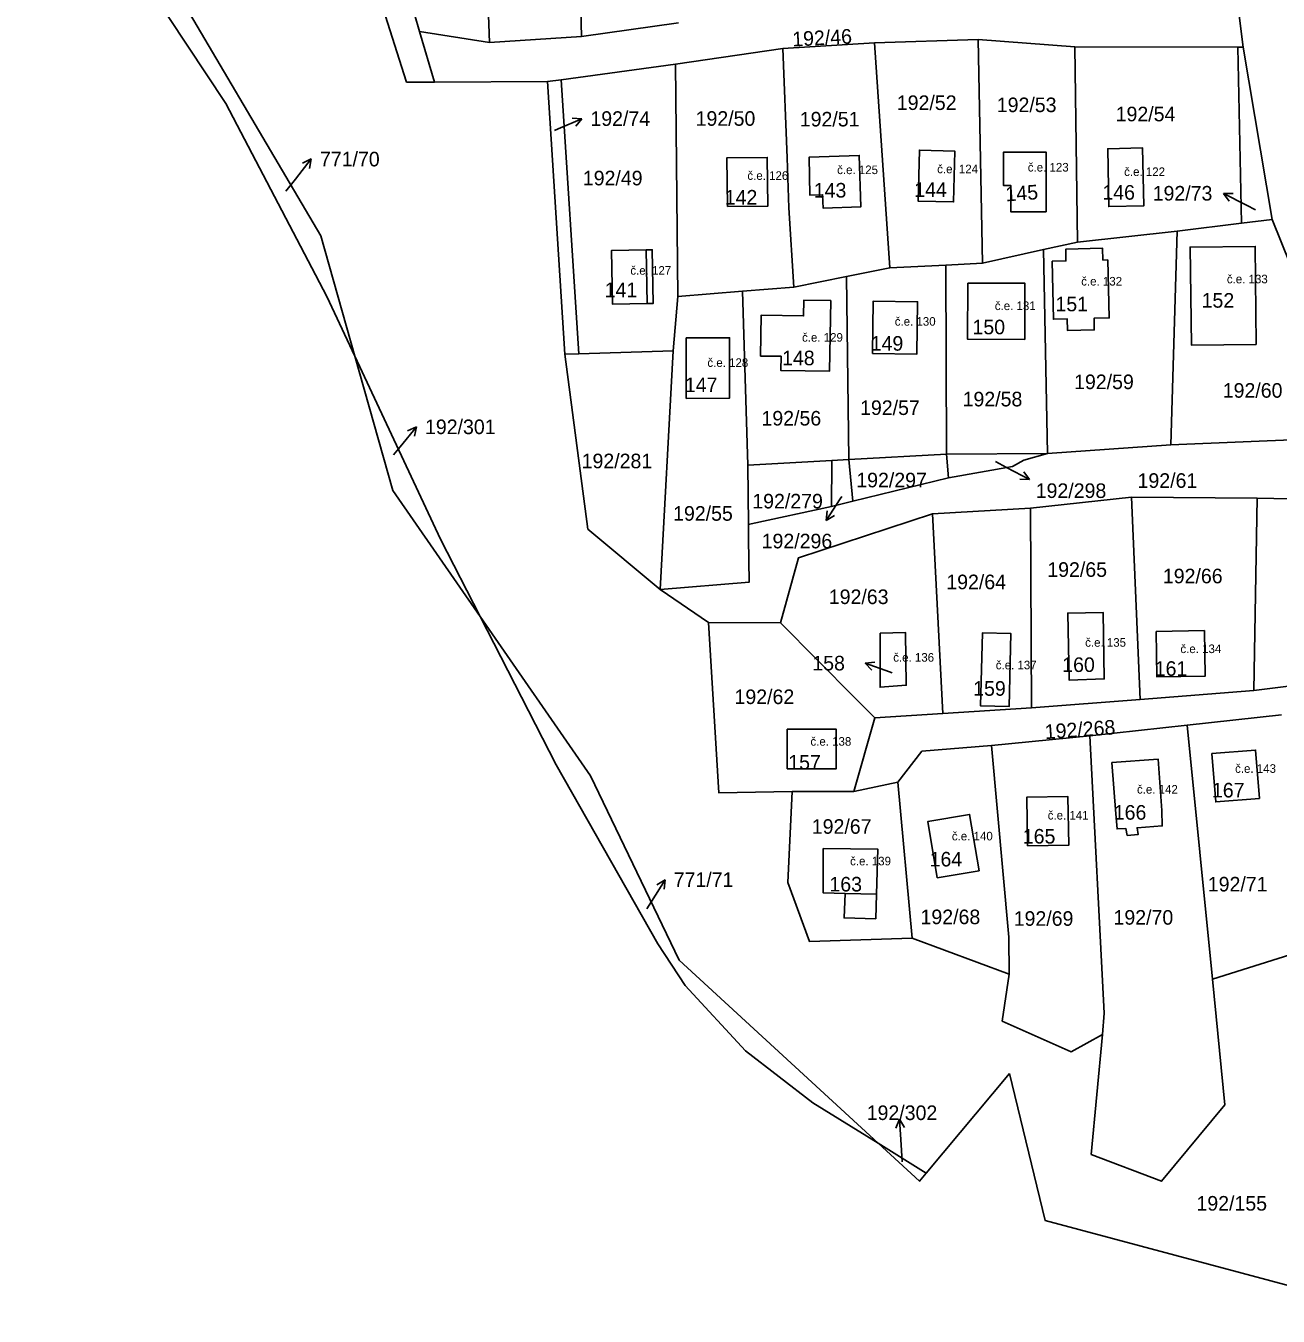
# Model space of a CAD drawing. Extents: x -887272 to -877616, y -1026687 to -1019819.
# Drawn here: x -882540.1 to -882394.3, y -1024320.7 to -1024170.3 of the extents above; entities that cross this region are included whole.
import ezdxf

# ---------------------------------------------------------------- set-up
doc = ezdxf.new("R2010")
doc.units = 0
for name, color, linetype in [('Definiční body', 7, 'Continuous'), ('Hranice parcel', 7, 'Continuous'), ('Parcelní čísla', 7, 'Continuous'), ('Polygon budovy', 7, 'Continuous'), ('Pop  PČ popisy', 7, 'Continuous'), ('Vnitřní kresba', 7, 'Continuous')]:
    doc.layers.add(name, color=color, linetype=linetype)

msp = doc.modelspace()

# ---------------------------------------------------------------- linework, layer by layer
at = {"layer": 'Hranice parcel'}
for p, q in [((-882487.23, -1024142.35), (-882486.14, -1024172.29)), ((-882476.32, -1024141.77), (-882475.42, -1024171.58)), ((-882398.41, -1024172.81), (-882399.41, -1024164.66)), ((-882475.42, -1024171.58), (-882464.13, -1024169.99)), ((-882494.31, -1024171), (-882486.14, -1024172.29)), ((-882492.56, -1024176.88), (-882494.31, -1024171)), ((-882486.14, -1024172.29), (-882475.42, -1024171.58)), ((-882452, -1024172.98), (-882441.31, -1024172.32)), ((-882441.31, -1024172.32), (-882429.24, -1024171.93)), ((-882439.54, -1024198.54), (-882441.31, -1024172.32)), ((-882429.24, -1024171.93), (-882417.98, -1024172.8)), ((-882428.76, -1024197.98), (-882429.24, -1024171.93)), ((-882464.49, -1024174.79), (-882452, -1024172.98)), ((-882417.98, -1024172.8), (-882399, -1024172.81)), ((-882417.69, -1024195.54), (-882417.98, -1024172.8)), ((-882399, -1024172.81), (-882398.41, -1024172.81)), ((-882398.58, -1024193.32), (-882399, -1024172.81)), ((-882395.01, -1024192.91), (-882398.41, -1024172.81)), ((-882477.79, -1024176.61), (-882464.49, -1024174.79)), ((-882464.21, -1024201.86), (-882464.49, -1024174.79)), ((-882492.56, -1024176.88), (-882479.41, -1024176.83)), ((-882479.41, -1024176.83), (-882477.79, -1024176.61)), ((-882479.41, -1024176.83), (-882477.36, -1024208.58)), ((-882477.79, -1024176.61), (-882475.73, -1024208.53)), ((-882406.07, -1024194.26), (-882398.58, -1024193.32)), ((-882395.01, -1024192.91), (-882398.58, -1024193.32)), ((-882384.85, -1024218.23), (-882395.01, -1024192.91)), ((-882417.69, -1024195.54), (-882406.07, -1024194.26)), ((-882406.81, -1024219.16), (-882406.07, -1024194.26)), ((-882428.76, -1024197.98), (-882421.63, -1024196.41)), ((-882421.63, -1024196.41), (-882417.69, -1024195.54)), ((-882421.19, -1024220.14), (-882421.63, -1024196.41)), ((-882433.01, -1024198.2), (-882428.76, -1024197.98)), ((-882444.57, -1024199.55), (-882439.54, -1024198.54)), ((-882439.54, -1024198.54), (-882433.01, -1024198.2)), ((-882432.93, -1024220.23), (-882433.01, -1024198.2)), ((-882456.7, -1024201.26), (-882450.72, -1024200.78)), ((-882450.72, -1024200.78), (-882444.57, -1024199.55)), ((-882444.31, -1024220.86), (-882444.57, -1024199.55)), ((-882464.78, -1024208.18), (-882464.21, -1024201.86)), ((-882464.21, -1024201.86), (-882456.7, -1024201.26)), ((-882456.08, -1024221.52), (-882456.7, -1024201.26)), ((-882477.36, -1024208.58), (-882475.73, -1024208.53)), ((-882475.73, -1024208.53), (-882464.78, -1024208.18)), ((-882464.78, -1024208.18), (-882466.28, -1024236)), ((-882441.55, -1024208.49), (-882436.39, -1024208.57)), ((-882463.24, -1024213.74), (-882458.22, -1024213.73)), ((-882406.81, -1024219.16), (-882384.85, -1024218.23)), ((-882444.31, -1024220.86), (-882432.93, -1024220.23)), ((-882432.93, -1024220.23), (-882421.19, -1024220.14)), ((-882432.7, -1024223), (-882432.93, -1024220.23)), ((-882421.19, -1024220.14), (-882406.81, -1024219.16)), ((-882456.08, -1024221.52), (-882446.3, -1024220.97)), ((-882456, -1024228.42), (-882456.08, -1024221.52)), ((-882446.3, -1024220.97), (-882444.31, -1024220.86)), ((-882443.83, -1024225.73), (-882444.31, -1024220.86)), ((-882443.83, -1024225.73), (-882432.7, -1024223)), ((-882446.34, -1024226.32), (-882443.83, -1024225.73)), ((-882423.15, -1024226.52), (-882434.56, -1024227.19)), ((-882411.4, -1024225.24), (-882423.15, -1024226.52)), ((-882423.04, -1024249.77), (-882423.15, -1024226.52)), ((-882410.38, -1024248.8), (-882411.4, -1024225.24)), ((-882396.78, -1024225.38), (-882411.4, -1024225.24)), ((-882397.17, -1024247.78), (-882396.78, -1024225.38)), ((-882396.78, -1024225.38), (-882382.84, -1024225.57)), ((-882433.35, -1024250.44), (-882434.56, -1024227.19)), ((-882455.98, -1024230.05), (-882456, -1024228.42)), ((-882466.28, -1024236), (-882460.64, -1024239.85)), ((-882452.28, -1024239.89), (-882460.64, -1024239.85)), ((-882423.04, -1024249.77), (-882410.38, -1024248.8)), ((-882410.38, -1024248.8), (-882397.17, -1024247.78)), ((-882441.28, -1024250.96), (-882433.35, -1024250.44)), ((-882433.35, -1024250.44), (-882423.04, -1024249.77)), ((-882393.92, -1024250.6), (-882404.93, -1024251.81)), ((-882443.73, -1024259.52), (-882441.28, -1024250.96)), ((-882404.93, -1024251.81), (-882416.23, -1024253.06)), ((-882401.95, -1024281.38), (-882404.93, -1024251.81)), ((-882416.23, -1024253.06), (-882427.71, -1024254.18)), ((-882450.92, -1024259.54), (-882443.73, -1024259.52)), ((-882438.6, -1024258.43), (-882443.73, -1024259.52)), ((-882436.92, -1024276.61), (-882438.6, -1024258.43)), ((-882434.02, -1024269.59), (-882429.14, -1024268.77)), ((-882436.92, -1024276.61), (-882425.64, -1024280.82)), ((-882401.95, -1024281.38), (-882392.22, -1024278.32)), ((-882435.31, -1024303.99), (-882425.59, -1024292.38)), ((-882435.31, -1024303.99), (-882440.89, -1024300.52))]:
    msp.add_line(p, q, dxfattribs=at)
for points in [[(-882497.59, -1024143.48), (-882497.2, -1024160.85), (-882494.31, -1024171)], [(-882501.82, -1024208.81), (-882505.78, -1024194.82), (-882525.14, -1024161.92), (-882540.14, -1024146.21)], [(-882540.14, -1024146.21), (-882538.86, -1024147.89), (-882532.4, -1024155.87), (-882516.84, -1024179.4), (-882505.08, -1024201.85), (-882501.82, -1024208.81)], [(-882514.25, -1024146.09), (-882509.29, -1024158.43), (-882505.52, -1024158.39), (-882501.29, -1024159.64), (-882495.81, -1024176.89), (-882492.56, -1024176.88)], [(-882450.72, -1024200.78), (-882451.31, -1024191.54), (-882451.49, -1024185.7), (-882452, -1024172.98)], [(-882458.45, -1024191.4), (-882453.75, -1024191.36), (-882453.8, -1024185.66), (-882458.5, -1024185.7), (-882458.45, -1024191.4)], [(-882443.09, -1024185.44), (-882448.92, -1024185.62), (-882448.86, -1024190.05), (-882447.36, -1024190.01), (-882447.31, -1024191.56), (-882442.91, -1024191.42), (-882443.09, -1024185.44)], [(-882432.12, -1024190.85), (-882431.98, -1024184.92), (-882436.1, -1024184.82), (-882436.24, -1024190.75), (-882432.12, -1024190.85)], [(-882426.3, -1024185.04), (-882426.31, -1024188.92), (-882425.46, -1024188.92), (-882425.45, -1024192), (-882421.34, -1024192), (-882421.34, -1024185.05), (-882426.3, -1024185.04)], [(-882410.1, -1024184.56), (-882414.17, -1024184.65), (-882414.04, -1024191.4), (-882409.97, -1024191.32), (-882410.1, -1024184.56)], [(-882471.96, -1024196.52), (-882471.84, -1024202.76), (-882467.79, -1024202.68), (-882467.09, -1024202.67), (-882467.19, -1024196.43), (-882467.91, -1024196.44), (-882471.96, -1024196.52)], [(-882425.59, -1024292.38), (-882421.44, -1024309.52), (-882387.34, -1024318.62), (-882335.2, -1024317.62), (-882324.6, -1024318.36), (-882301.38, -1024320.66), (-882228.26, -1024295.72), (-882166.04, -1024261.72), (-882132.4, -1024219.02), (-882083.16, -1024195.4)], [(-882413.98, -1024204.36), (-882414.17, -1024197.61), (-882414.72, -1024197.63), (-882414.77, -1024196.25), (-882419.06, -1024196.36), (-882419.03, -1024197.72), (-882420.63, -1024197.76), (-882420.48, -1024204.51), (-882418.87, -1024204.47), (-882418.84, -1024205.83), (-882415.73, -1024205.76), (-882415.76, -1024204.4), (-882413.98, -1024204.36)], [(-882396.87, -1024207.45), (-882396.99, -1024196.04), (-882404.57, -1024196.12), (-882404.42, -1024207.52), (-882396.87, -1024207.45)], [(-882430.47, -1024200.31), (-882430.5, -1024206.83), (-882423.82, -1024206.86), (-882423.82, -1024200.3), (-882430.47, -1024200.31)], [(-882454.59, -1024208.81), (-882452.2, -1024208.83), (-882452.23, -1024210.47), (-882446.58, -1024210.58), (-882446.41, -1024202.35), (-882449.54, -1024202.29), (-882449.57, -1024204.13), (-882454.5, -1024204.04), (-882454.59, -1024208.81)], [(-882436.39, -1024208.57), (-882436.3, -1024202.48), (-882441.46, -1024202.4), (-882441.55, -1024208.49)], [(-882458.22, -1024213.73), (-882458.2, -1024206.68), (-882463.25, -1024206.69), (-882463.24, -1024213.74)], [(-882501.82, -1024208.81), (-882497.39, -1024224.47), (-882487.23, -1024239.16)], [(-882487.23, -1024239.16), (-882491.84, -1024230.13), (-882501.82, -1024208.81)], [(-882477.36, -1024208.58), (-882474.69, -1024228.97), (-882466.28, -1024236)], [(-882432.7, -1024223), (-882425.25, -1024221.66), (-882423.95, -1024220.93), (-882421.19, -1024220.14)], [(-882446.34, -1024226.32), (-882446.3, -1024221.18), (-882446.3, -1024220.97)], [(-882456, -1024228.42), (-882455.67, -1024228.35), (-882446.34, -1024226.32)], [(-882434.56, -1024227.19), (-882450.17, -1024232.3), (-882452.28, -1024239.89)], [(-882466.28, -1024236), (-882455.92, -1024235.15), (-882455.98, -1024230.05)], [(-882440.89, -1024300.52), (-882464.08, -1024279.19), (-882474.4, -1024257.7), (-882487.23, -1024239.16)], [(-882487.23, -1024239.16), (-882478.4, -1024256.44), (-882466.55, -1024277.28), (-882463.36, -1024282.12), (-882456.33, -1024289.73), (-882448.49, -1024295.79), (-882440.89, -1024300.52)], [(-882460.64, -1024239.85), (-882459.44, -1024259.7), (-882450.92, -1024259.54)], [(-882441.28, -1024250.96), (-882443.66, -1024248.58), (-882452.28, -1024239.89)], [(-882418.81, -1024238.75), (-882418.66, -1024246.56), (-882414.56, -1024246.42), (-882414.71, -1024238.67), (-882418.81, -1024238.75)], [(-882440.66, -1024241.1), (-882440.68, -1024247.38), (-882437.62, -1024247.16), (-882437.7, -1024241.02), (-882440.66, -1024241.1)], [(-882428.97, -1024249.57), (-882425.65, -1024249.65), (-882425.44, -1024241.14), (-882428.76, -1024241.06), (-882428.97, -1024249.57)], [(-882408.51, -1024240.88), (-882408.43, -1024246.19), (-882402.82, -1024246.1), (-882402.9, -1024240.79), (-882408.51, -1024240.88)], [(-882397.17, -1024247.78), (-882381.94, -1024245.87), (-882380.49, -1024244.25)], [(-882451.48, -1024252.28), (-882451.48, -1024256.88), (-882445.78, -1024256.88), (-882445.78, -1024252.28), (-882451.48, -1024252.28)], [(-882414.79, -1024287.85), (-882414.56, -1024285.34), (-882416.23, -1024253.06)], [(-882427.71, -1024254.18), (-882435.8, -1024254.84), (-882438.6, -1024258.43)], [(-882425.64, -1024280.82), (-882425.69, -1024276.49), (-882427.71, -1024254.18)], [(-882396.94, -1024254.71), (-882402.03, -1024255.11), (-882401.59, -1024260.74), (-882396.5, -1024260.34), (-882396.94, -1024254.71)], [(-882411.9, -1024264.66), (-882410.63, -1024264.56), (-882410.75, -1024263.76), (-882407.81, -1024263.55), (-882407.87, -1024261.75), (-882408.3, -1024255.75), (-882413.68, -1024256.16), (-882413.22, -1024262.15), (-882413.07, -1024263.89), (-882412.07, -1024263.84), (-882411.9, -1024264.66)], [(-882450.92, -1024259.54), (-882451.4, -1024270.13), (-882448.89, -1024276.99), (-882436.92, -1024276.61)], [(-882418.79, -1024260.13), (-882423.59, -1024260.21), (-882423.5, -1024265.86), (-882418.68, -1024265.78), (-882418.79, -1024260.13)], [(-882429.14, -1024268.77), (-882430.24, -1024262.21), (-882435.12, -1024263.03), (-882434.02, -1024269.59)], [(-882441.17, -1024274.38), (-882441.08, -1024271.49), (-882440.92, -1024266.26), (-882447.28, -1024266.19), (-882447.29, -1024271.35), (-882444.75, -1024271.41), (-882444.86, -1024274.27), (-882441.17, -1024274.38)], [(-882414.79, -1024287.85), (-882418.44, -1024289.85), (-882426.45, -1024286.28), (-882425.64, -1024280.82)], [(-882401.95, -1024281.38), (-882400.53, -1024296.03), (-882407.89, -1024304.93), (-882416.08, -1024301.82), (-882414.79, -1024287.85)], [(-882440.89, -1024300.52), (-882436.1, -1024304.93), (-882435.31, -1024303.99)]]:
    msp.add_lwpolyline(points, dxfattribs=at)
at = {"layer": 'Polygon budovy'}
for points in [[(-882458.45, -1024191.4), (-882453.75, -1024191.36), (-882453.8, -1024185.66), (-882458.5, -1024185.7)], [(-882447.31, -1024191.56), (-882442.91, -1024191.42), (-882443.09, -1024185.44), (-882448.92, -1024185.62), (-882448.86, -1024190.05), (-882447.36, -1024190.01)], [(-882436.1, -1024184.82), (-882436.24, -1024190.75), (-882432.12, -1024190.85), (-882431.98, -1024184.92)], [(-882426.31, -1024188.92), (-882425.46, -1024188.92), (-882425.45, -1024192), (-882421.34, -1024192), (-882421.34, -1024185.05), (-882426.3, -1024185.04)], [(-882414.04, -1024191.4), (-882409.97, -1024191.32), (-882410.1, -1024184.56), (-882414.17, -1024184.65)], [(-882471.84, -1024202.76), (-882467.79, -1024202.68), (-882467.91, -1024196.44), (-882471.96, -1024196.52)], [(-882414.72, -1024197.63), (-882414.77, -1024196.25), (-882419.06, -1024196.36), (-882419.03, -1024197.72), (-882420.63, -1024197.76), (-882420.48, -1024204.51), (-882418.87, -1024204.47), (-882418.84, -1024205.83), (-882415.73, -1024205.76), (-882415.76, -1024204.4), (-882413.98, -1024204.36), (-882414.17, -1024197.61)], [(-882396.87, -1024207.45), (-882396.99, -1024196.04), (-882404.57, -1024196.12), (-882404.42, -1024207.52)], [(-882430.47, -1024200.31), (-882430.5, -1024206.83), (-882423.82, -1024206.86), (-882423.82, -1024200.3)], [(-882454.5, -1024204.04), (-882454.59, -1024208.81), (-882452.2, -1024208.83), (-882452.23, -1024210.47), (-882446.58, -1024210.58), (-882446.41, -1024202.35), (-882449.54, -1024202.29), (-882449.57, -1024204.13)], [(-882441.55, -1024208.49), (-882436.39, -1024208.57), (-882436.3, -1024202.48), (-882441.46, -1024202.4)], [(-882463.24, -1024213.74), (-882458.22, -1024213.73), (-882458.2, -1024206.68), (-882463.25, -1024206.69)], [(-882414.56, -1024246.42), (-882414.71, -1024238.67), (-882418.81, -1024238.75), (-882418.66, -1024246.56)], [(-882437.62, -1024247.16), (-882437.7, -1024241.02), (-882440.66, -1024241.1), (-882440.68, -1024247.38)], [(-882428.76, -1024241.06), (-882428.97, -1024249.57), (-882425.65, -1024249.65), (-882425.44, -1024241.14)], [(-882408.51, -1024240.88), (-882408.43, -1024246.19), (-882402.82, -1024246.1), (-882402.9, -1024240.79)], [(-882445.78, -1024256.88), (-882445.78, -1024252.28), (-882451.48, -1024252.28), (-882451.48, -1024256.88)], [(-882401.59, -1024260.74), (-882396.5, -1024260.34), (-882396.94, -1024254.71), (-882402.03, -1024255.11)], [(-882410.75, -1024263.76), (-882407.81, -1024263.55), (-882407.87, -1024261.75), (-882408.3, -1024255.75), (-882413.68, -1024256.16), (-882413.22, -1024262.15), (-882413.07, -1024263.89), (-882412.07, -1024263.84), (-882411.9, -1024264.66), (-882410.63, -1024264.56)], [(-882423.5, -1024265.86), (-882418.68, -1024265.78), (-882418.79, -1024260.13), (-882423.59, -1024260.21)], [(-882434.02, -1024269.59), (-882429.14, -1024268.77), (-882430.24, -1024262.21), (-882435.12, -1024263.03)], [(-882444.75, -1024271.41), (-882441.08, -1024271.49), (-882440.92, -1024266.26), (-882447.28, -1024266.19), (-882447.29, -1024271.35)]]:
    msp.add_lwpolyline(points, close=True, dxfattribs=at)
at = {"layer": 'Pop  PČ popisy'}
for p, q in [((-882478.15, -1024182.33), (-882475.39, -1024181.16)), ((-882475.39, -1024181.16), (-882476.51, -1024181.09)), ((-882475.39, -1024181.16), (-882476.11, -1024182.01)), ((-882478.58, -1024182.52), (-882478.15, -1024182.33)), ((-882508.75, -1024188.21), (-882506.9, -1024185.84)), ((-882506.9, -1024185.84), (-882507.91, -1024186.33)), ((-882506.9, -1024185.84), (-882507.12, -1024186.94)), ((-882509.85, -1024189.6), (-882508.75, -1024188.21)), ((-882398.01, -1024191.22), (-882400.68, -1024189.86)), ((-882400.68, -1024189.86), (-882399.56, -1024189.87)), ((-882400.68, -1024189.86), (-882400.02, -1024190.76)), ((-882396.94, -1024191.77), (-882398.01, -1024191.22)), ((-882496.55, -1024219.38), (-882494.66, -1024217.05)), ((-882494.66, -1024217.05), (-882495.68, -1024217.51)), ((-882494.66, -1024217.05), (-882494.9, -1024218.14)), ((-882497.31, -1024220.32), (-882496.55, -1024219.38)), ((-882427.22, -1024221.1), (-882425.94, -1024221.78)), ((-882425.94, -1024221.78), (-882423.29, -1024223.19)), ((-882423.29, -1024223.19), (-882424.41, -1024223.16)), ((-882423.29, -1024223.19), (-882423.94, -1024222.28)), ((-882445.32, -1024225.43), (-882446.95, -1024227.95)), ((-882445.14, -1024225.16), (-882445.32, -1024225.43)), ((-882446.95, -1024227.95), (-882446.83, -1024226.83)), ((-882446.95, -1024227.95), (-882445.99, -1024227.38)), ((-882442.4, -1024244.57), (-882441.29, -1024244.45)), ((-882439.58, -1024245.6), (-882442.4, -1024244.57)), ((-882442.4, -1024244.57), (-882441.63, -1024245.39)), ((-882439.26, -1024245.72), (-882439.58, -1024245.6)), ((-882467.28, -1024272.35), (-882465.69, -1024269.81)), ((-882465.69, -1024269.81), (-882466.65, -1024270.39)), ((-882465.69, -1024269.81), (-882465.8, -1024270.92)), ((-882467.82, -1024273.22), (-882467.28, -1024272.35)), ((-882438.41, -1024297.71), (-882438.84, -1024298.74)), ((-882438.2, -1024300.7), (-882438.41, -1024297.71)), ((-882438.41, -1024297.71), (-882437.84, -1024298.67)), ((-882438.08, -1024302.69), (-882438.2, -1024300.7))]:
    msp.add_line(p, q, dxfattribs=at)
at = {"layer": 'Vnitřní kresba'}
for p, q in [((-882467.91, -1024196.44), (-882467.79, -1024202.68)), ((-882444.75, -1024271.41), (-882441.08, -1024271.49))]:
    msp.add_line(p, q, dxfattribs=at)

# ---------------------------------------------------------------- texts
at = {"layer": 'Definiční body'}
for s, p in [('č.e. 126', (-882456.12, -1024188.28)), ('č.e. 125', (-882445.67, -1024187.61)), ('č.e. 124', (-882434.02, -1024187.51)), ('č.e. 123', (-882423.47, -1024187.31)), ('č.e. 122', (-882412.25, -1024187.83)), ('č.e. 127', (-882469.75, -1024199.33)), ('č.e. 133', (-882400.29, -1024200.33)), ('č.e. 132', (-882417.25, -1024200.59)), ('č.e. 131', (-882427.31, -1024203.45)), ('č.e. 130', (-882438.96, -1024205.27)), ('č.e. 129', (-882449.76, -1024207.13)), ('č.e. 128', (-882460.78, -1024210.07)), ('č.e. 135', (-882416.79, -1024242.67)), ('č.e. 134', (-882405.7, -1024243.41)), ('č.e. 136', (-882439.14, -1024244.41)), ('č.e. 137', (-882427.2, -1024245.3)), ('č.e. 138', (-882448.78, -1024254.2)), ('č.e. 143', (-882399.33, -1024257.36)), ('č.e. 142', (-882410.76, -1024259.78)), ('č.e. 141', (-882421.15, -1024262.8)), ('č.e. 140', (-882432.31, -1024265.23)), ('č.e. 139', (-882444.16, -1024268.14))]:
    msp.add_text(s, height=1, dxfattribs=at).set_placement(p)
at = {"layer": 'Parcelní čísla'}
for s, rotation, p in [('192/46', 3, (-882450.85, -1024172.75)), ('145', 4, (-882426.01, -1024190.79)), ('192/268', 4, (-882421.43, -1024253.44))]:
    msp.add_text(s, height=1.7, rotation=rotation, dxfattribs=at).set_placement(p)
for s, p in [('192/52', (-882438.72, -1024180.14)), ('192/53', (-882427.08, -1024180.39)), ('192/54', (-882413.24, -1024181.46)), ('192/74', (-882474.4, -1024181.99)), ('192/50', (-882462.15, -1024181.98)), ('192/51', (-882450.02, -1024182.06)), ('771/70', (-882505.89, -1024186.71)), ('192/49', (-882475.28, -1024188.92)), ('143', (-882448.39, -1024190.34)), ('144', (-882436.69, -1024190.26)), ('146', (-882414.79, -1024190.59)), ('192/73', (-882408.93, -1024190.69)), ('142', (-882458.76, -1024191.16)), ('141', (-882472.74, -1024201.95)), ('151', (-882420.25, -1024203.59)), ('152', (-882403.23, -1024203.17)), ('150', (-882429.91, -1024206.27)), ('149', (-882441.76, -1024208.18)), ('148', (-882452.08, -1024209.88)), ('147', (-882463.4, -1024213.01)), ('192/59', (-882418.08, -1024212.66)), ('192/58', (-882431.06, -1024214.67)), ('192/60', (-882400.77, -1024213.66)), ('192/57', (-882443, -1024215.67)), ('192/56', (-882454.48, -1024216.9)), ('192/301', (-882493.66, -1024217.9)), ('192/281', (-882475.42, -1024221.88)), ('192/297', (-882443.44, -1024224.1)), ('192/298', (-882422.55, -1024225.34)), ('192/61', (-882410.69, -1024224.16)), ('192/279', (-882455.55, -1024226.56)), ('192/55', (-882464.77, -1024227.99)), ('192/296', (-882454.46, -1024231.21)), ('192/65', (-882421.2, -1024234.53)), ('192/66', (-882407.74, -1024235.28)), ('192/64', (-882432.96, -1024235.97)), ('192/63', (-882446.64, -1024237.7)), ('158', (-882448.56, -1024245.43)), ('160', (-882419.46, -1024245.61)), ('161', (-882408.69, -1024246.06)), ('192/62', (-882457.62, -1024249.35)), ('159', (-882429.83, -1024248.38)), ('157', (-882451.36, -1024256.98)), ('167', (-882402.03, -1024260.23)), ('166', (-882413.46, -1024262.82)), ('192/67', (-882448.62, -1024264.46)), ('165', (-882424.05, -1024265.6)), ('164', (-882434.9, -1024268.27)), ('771/71', (-882464.7, -1024270.65)), ('163', (-882446.57, -1024271.18)), ('192/71', (-882402.51, -1024271.18)), ('192/68', (-882435.96, -1024274.99)), ('192/69', (-882425.11, -1024275.18)), ('192/70', (-882413.49, -1024275.05)), ('192/302', (-882442.23, -1024297.81)), ('192/155', (-882403.83, -1024308.36))]:
    msp.add_text(s, height=1.7, dxfattribs=at).set_placement(p)

doc.saveas('drawing.dxf')
